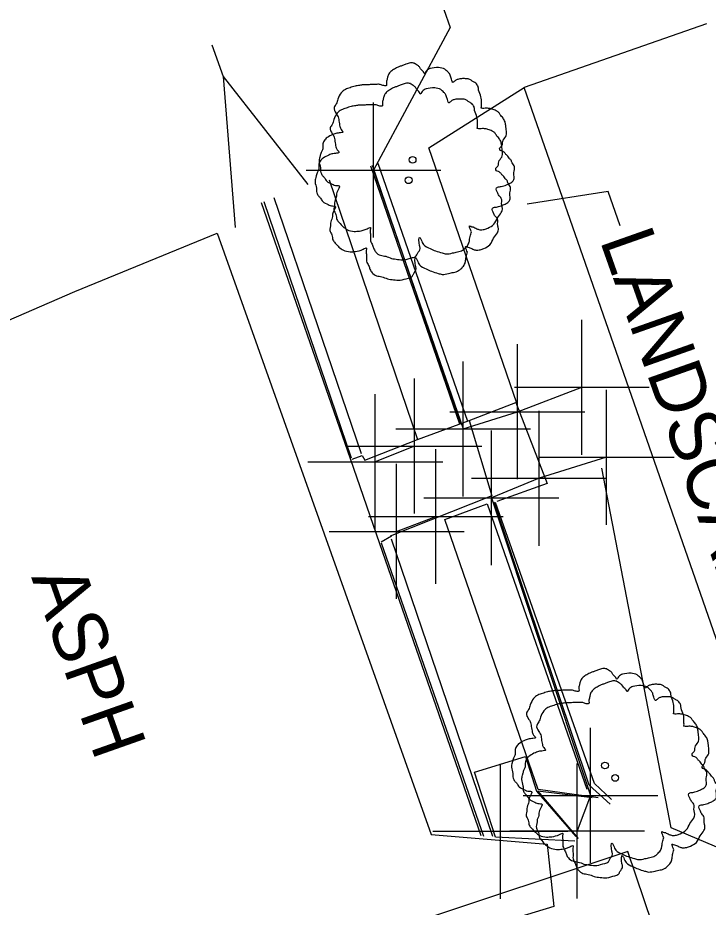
# Model space of a CAD drawing. Extents: x 2004847 to 2009016, y 1134161 to 1140101.
# Drawn here: x 2005808.7 to 2005859.9, y 1138108.9 to 1138174.9 of the extents above; entities that cross this region are included whole.
import ezdxf

# ---------------------------------------------------------------- set-up
doc = ezdxf.new("R2010")
doc.units = 0
for name, color, linetype in [('RD_EX_Bldg', 7, 'Continuous'), ('RD_EX_BldgApp', 7, 'Continuous'), ('RD_EX_Conc', 7, 'Continuous'), ('RD_EX_Driveway', 7, 'Continuous'), ('RD_EX_DV_Prop_txCode', 7, 'Continuous'), ('RD_EX_Misc', 7, 'Continuous'), ('RD_EX_VEG', 7, 'Continuous'), ('RD_Sketch3', 7, 'Continuous')]:
    doc.layers.add(name, color=color, linetype=linetype)

msp = doc.modelspace()

# ---------------------------------------------------------------- linework, layer by layer
at = {"layer": 'RD_EX_Bldg'}
for p in [(2005859.818, 1138174.404), (2005866.841, 1138110.735)]:
    msp.add_line(p, (2005846.292, 1138169.689), dxfattribs=at)
at = {"layer": 'RD_EX_BldgApp'}
msp.add_lwpolyline([(2005842.212, 1138145.001), (2005845.669, 1138146.333), (2005847.999, 1138140.323), (2005844.263, 1138138.993)], dxfattribs=at)
msp.add_lwpolyline([(2005806.418, 1138097.227), (2005810.884, 1138082.901), (2005858.804, 1138098.787), (2005853.984, 1138113.042)], close=True, dxfattribs=at)
at = {"layer": 'RD_EX_Conc'}
for p, q in [((2005835.439, 1138164.08), (2005842.087, 1138144.96)), ((2005834.903, 1138163.888), (2005841.503, 1138144.757)), ((2005835.018, 1138163.927), (2005841.583, 1138144.785)), ((2005831.837, 1138162.853), (2005838.398, 1138143.584)), ((2005834.23, 1138142.524), (2005827.758, 1138161.505)), ((2005833.49, 1138142.212), (2005827.024, 1138161.21)), ((2005843.544, 1138138.815), (2005850.941, 1138117.672)), ((2005843.294, 1138114.166), (2005835.728, 1138135.915)), ((2005843.981, 1138114.174), (2005836.454, 1138136.206))]:
    msp.add_line(p, q, dxfattribs=at)
for points in [[(2005843.113, 1138114.22), (2005835.604, 1138135.853), (2005833.422, 1138142.151), (2005826.827, 1138161.152)], [(2005833.546, 1138142.128), (2005834.283, 1138142.42), (2005834.472, 1138142.054), (2005838.398, 1138143.584), (2005842.212, 1138145.001), (2005843.89, 1138139.424), (2005836.348, 1138136.438), (2005836.459, 1138136.433), (2005835.691, 1138135.983)], [(2005852.678, 1138116.568), (2005851.112, 1138117.98), (2005844.067, 1138138.956)], [(2005851.776, 1138117.023), (2005847.324, 1138117.658), (2005840.411, 1138137.675), (2005843.544, 1138138.815)], [(2005852.787, 1138116.9), (2005851.523, 1138118.105), (2005844.175, 1138138.927)], [(2005850.058, 1138113.813), (2005844.166, 1138114.111), (2005842.613, 1138118.927), (2005846.387, 1138120.092), (2005847.201, 1138117.524), (2005850.127, 1138114.175)], [(2005850.316, 1138114.013), (2005847.31, 1138117.558), (2005851.337, 1138117.052)]]:
    msp.add_lwpolyline(points, dxfattribs=at)
at = {"layer": 'RD_EX_Driveway'}
msp.add_lwpolyline([(2005791.893, 1138145.432), (2005812.971, 1138154.559), (2005823.54, 1138158.89), (2005830.037, 1138140.621), (2005839.408, 1138114.322), (2005848.012, 1138113.597), (2005848.51, 1138108.974), (2005830.681, 1138103.556), (2005807.756, 1138095.979)], dxfattribs=at)
at = {"layer": 'RD_EX_DV_Prop_txCode'}
for p, q in [((2005835.122, 1138158.571), (2005835.122, 1138168.571)), ((2005830.122, 1138163.571), (2005840.122, 1138163.571)), ((2005850.578, 1138142.469), (2005850.578, 1138152.469)), ((2005845.795, 1138140.658), (2005845.795, 1138150.658)), ((2005841.768, 1138139.379), (2005841.768, 1138149.379)), ((2005838.153, 1138138.107), (2005838.153, 1138148.107)), ((2005835.255, 1138136.945), (2005835.255, 1138146.945)), ((2005845.578, 1138147.469), (2005855.578, 1138147.469)), ((2005852.416, 1138137.276), (2005852.416, 1138147.276)), ((2005840.795, 1138145.658), (2005850.795, 1138145.658)), ((2005847.403, 1138135.72), (2005847.403, 1138145.72)), ((2005836.768, 1138144.379), (2005846.768, 1138144.379)), ((2005843.867, 1138134.27), (2005843.867, 1138144.27)), ((2005833.153, 1138143.107), (2005843.153, 1138143.107)), ((2005839.749, 1138132.889), (2005839.749, 1138142.889)), ((2005847.416, 1138142.276), (2005857.416, 1138142.276)), ((2005830.255, 1138141.945), (2005840.255, 1138141.945)), ((2005836.837, 1138131.785), (2005836.837, 1138141.785)), ((2005842.403, 1138140.72), (2005852.403, 1138140.72)), ((2005838.867, 1138139.27), (2005848.867, 1138139.27)), ((2005834.749, 1138137.889), (2005844.749, 1138137.889)), ((2005831.837, 1138136.785), (2005841.837, 1138136.785)), ((2005851.223, 1138112.211), (2005851.223, 1138122.211)), ((2005844.531, 1138109.554), (2005844.531, 1138119.554)), ((2005850.224, 1138109.579), (2005850.224, 1138119.579)), ((2005846.223, 1138117.211), (2005856.223, 1138117.211)), ((2005839.531, 1138114.554), (2005849.531, 1138114.554)), ((2005845.224, 1138114.579), (2005855.224, 1138114.579))]:
    msp.add_line(p, q, dxfattribs=at)
at = {"layer": 'RD_EX_Misc'}
for p, q in [((2005838.153, 1138143.107), (2005835.255, 1138141.945)), ((2005836.837, 1138136.785), (2005839.749, 1138137.889))]:
    msp.add_line(p, q, dxfattribs=at)
for points in [[(2005835.122, 1138163.571), (2005841.768, 1138144.379), (2005845.795, 1138145.658), (2005850.578, 1138147.469)], [(2005852.416, 1138142.276), (2005847.403, 1138140.72), (2005843.867, 1138139.27), (2005851.223, 1138117.211), (2005850.224, 1138114.579)]]:
    msp.add_lwpolyline(points, dxfattribs=at)
at = {"layer": 'RD_EX_VEG'}
for points in [[(2005845.754, 1138146.288), (2005839.234, 1138165.213), (2005846.292, 1138169.689)], [(2005866.841, 1138110.735), (2005857.201, 1138114.796), (2005852.068, 1138141.468)]]:
    msp.add_lwpolyline(points, dxfattribs=at)
for centre, radius in [((2005838.025, 1138164.327), 0.25), ((2005838.012, 1138164.308), 0.0001), ((2005837.729, 1138162.815), 0.25), ((2005837.717, 1138162.796), 0.0001), ((2005852.293, 1138119.427), 0.25), ((2005852.28, 1138119.408), 0.0001), ((2005853.046, 1138118.51), 0.25), ((2005853.033, 1138118.491), 0.0001)]:
    msp.add_circle(centre, radius, dxfattribs=at)
for points in [[(2005838.157, 1138171.494), (2005837.857, 1138171.519), (2005837.532, 1138171.419), (2005837.282, 1138171.319), (2005837.057, 1138171.244), (2005836.833, 1138171.144), (2005836.533, 1138170.97), (2005836.308, 1138170.77), (2005836.183, 1138170.52), (2005836.133, 1138170.295), (2005836.083, 1138170.02), (2005836.083, 1138169.845), (2005835.958, 1138169.82), (2005835.808, 1138169.845), (2005835.558, 1138169.92), (2005835.308, 1138169.92), (2005835.058, 1138169.92), (2005834.708, 1138169.895), (2005834.359, 1138169.895), (2005834.084, 1138169.845), (2005833.759, 1138169.795), (2005833.384, 1138169.67), (2005833.034, 1138169.545), (2005832.734, 1138169.295), (2005832.484, 1138168.82), (2005832.359, 1138168.471), (2005832.21, 1138168.221), (2005832.359, 1138167.771), (2005832.534, 1138167.421), (2005832.559, 1138167.221), (2005832.634, 1138166.796), (2005832.734, 1138166.571), (2005832.859, 1138166.371), (2005832.784, 1138166.347), (2005832.409, 1138166.297), (2005832.11, 1138166.197), (2005831.685, 1138165.972), (2005831.46, 1138165.747), (2005831.36, 1138165.422), (2005831.335, 1138165.072), (2005831.235, 1138164.872), (2005831.16, 1138164.597), (2005831.135, 1138164.522), (2005831.085, 1138164.197), (2005831.185, 1138163.748), (2005831.21, 1138163.398), (2005831.335, 1138163.173), (2005831.485, 1138162.998), (2005831.66, 1138162.748), (2005832.06, 1138162.523), (2005832.384, 1138162.423), (2005832.584, 1138162.398), (2005832.409, 1138161.898), (2005832.359, 1138161.549), (2005832.235, 1138161.149), (2005832.235, 1138161.074), (2005832.185, 1138160.599), (2005832.334, 1138160.274), (2005832.409, 1138159.899), (2005832.584, 1138159.674), (2005832.859, 1138159.375), (2005833.184, 1138159.15), (2005833.684, 1138159.025), (2005834.084, 1138159.05), (2005834.659, 1138159.225), (2005834.908, 1138159.3), (2005834.883, 1138159.125), (2005834.908, 1138158.75), (2005834.908, 1138158.325), (2005835.058, 1138158), (2005835.158, 1138157.725), (2005835.308, 1138157.475), (2005835.633, 1138157.251), (2005836.033, 1138157.176), (2005836.458, 1138157.026), (2005836.908, 1138156.951), (2005837.407, 1138156.926), (2005838.007, 1138157.076), (2005838.282, 1138157.201), (2005838.382, 1138157.375), (2005838.582, 1138157.75), (2005838.532, 1138157.975), (2005838.557, 1138158.575), (2005838.657, 1138158.4), (2005838.832, 1138158.05), (2005839.331, 1138157.75), (2005839.731, 1138157.575), (2005840.206, 1138157.425), (2005840.506, 1138157.35), (2005840.981, 1138157.425), (2005841.356, 1138157.5), (2005841.73, 1138157.625), (2005842.03, 1138157.9), (2005842.205, 1138158.175), (2005842.255, 1138158.45), (2005842.33, 1138158.825), (2005842.38, 1138159)], [(2005842.38, 1138159), (2005842.305, 1138159.175), (2005842.255, 1138159.425), (2005842.33, 1138159.4), (2005842.505, 1138159.35), (2005842.78, 1138159.225), (2005843.005, 1138159.15), (2005843.33, 1138159.175), (2005843.605, 1138159.275), (2005844.054, 1138159.55), (2005844.329, 1138160.024), (2005844.604, 1138160.424), (2005844.679, 1138160.749), (2005844.629, 1138160.974), (2005844.604, 1138161.474), (2005844.404, 1138161.724), (2005844.354, 1138161.848), (2005844.254, 1138162.248), (2005844.329, 1138162.298), (2005844.604, 1138162.348), (2005844.979, 1138162.473), (2005845.254, 1138162.598), (2005845.479, 1138162.773), (2005845.554, 1138162.998), (2005845.529, 1138163.398), (2005845.579, 1138163.798), (2005845.504, 1138163.948), (2005845.404, 1138164.097), (2005845.329, 1138164.297), (2005845.179, 1138164.447), (2005845.079, 1138164.597), (2005844.979, 1138164.697), (2005844.854, 1138164.847), (2005844.679, 1138164.972), (2005844.529, 1138165.022), (2005844.479, 1138165.172), (2005844.629, 1138165.372), (2005844.679, 1138165.472), (2005844.704, 1138165.697), (2005844.929, 1138166.047), (2005844.979, 1138166.446), (2005844.929, 1138166.871), (2005844.879, 1138167.146), (2005844.729, 1138167.421), (2005844.529, 1138167.671), (2005844.404, 1138167.846), (2005844.229, 1138167.971), (2005843.904, 1138168.096), (2005843.655, 1138168.146), (2005843.305, 1138168.146), (2005843.105, 1138168.196), (2005843.13, 1138168.246), (2005843.13, 1138168.396), (2005843.13, 1138168.671), (2005843.055, 1138169.12), (2005842.905, 1138169.62), (2005842.905, 1138169.645), (2005842.805, 1138169.895), (2005842.58, 1138170.095), (2005842.405, 1138170.195), (2005842.205, 1138170.32), (2005841.955, 1138170.345), (2005841.655, 1138170.345), (2005841.381, 1138170.295), (2005841.181, 1138170.195), (2005841.006, 1138170.07), (2005840.931, 1138170.22), (2005840.831, 1138170.52), (2005840.781, 1138170.67), (2005840.631, 1138170.845), (2005840.406, 1138171.044), (2005839.956, 1138171.169), (2005839.331, 1138171.094), (2005839.032, 1138170.895), (2005838.882, 1138170.72), (2005838.832, 1138170.845), (2005838.632, 1138171.044), (2005838.532, 1138171.219), (2005838.357, 1138171.344), (2005838.207, 1138171.444), (2005838.107, 1138171.494)], [(2005837.861, 1138169.982), (2005837.561, 1138170.007), (2005837.237, 1138169.907), (2005836.987, 1138169.807), (2005836.762, 1138169.732), (2005836.537, 1138169.632), (2005836.237, 1138169.457), (2005836.012, 1138169.257), (2005835.887, 1138169.008), (2005835.837, 1138168.783), (2005835.787, 1138168.508), (2005835.787, 1138168.333), (2005835.662, 1138168.308), (2005835.512, 1138168.333), (2005835.262, 1138168.408), (2005835.013, 1138168.408), (2005834.763, 1138168.408), (2005834.413, 1138168.383), (2005834.063, 1138168.383), (2005833.788, 1138168.333), (2005833.463, 1138168.283), (2005833.088, 1138168.158), (2005832.739, 1138168.033), (2005832.439, 1138167.783), (2005832.189, 1138167.308), (2005832.064, 1138166.958), (2005831.914, 1138166.709), (2005832.064, 1138166.259), (2005832.239, 1138165.909), (2005832.264, 1138165.709), (2005832.339, 1138165.284), (2005832.439, 1138165.059), (2005832.564, 1138164.859), (2005832.489, 1138164.834), (2005832.114, 1138164.784), (2005831.814, 1138164.684), (2005831.389, 1138164.46), (2005831.164, 1138164.235), (2005831.064, 1138163.91), (2005831.039, 1138163.56), (2005830.939, 1138163.36), (2005830.864, 1138163.085), (2005830.839, 1138163.01), (2005830.789, 1138162.685), (2005830.889, 1138162.235), (2005830.914, 1138161.886), (2005831.039, 1138161.661), (2005831.189, 1138161.486), (2005831.364, 1138161.236), (2005831.764, 1138161.011), (2005832.089, 1138160.911), (2005832.289, 1138160.886), (2005832.114, 1138160.386), (2005832.064, 1138160.036), (2005831.939, 1138159.637), (2005831.939, 1138159.562), (2005831.889, 1138159.087), (2005832.039, 1138158.762), (2005832.114, 1138158.387), (2005832.289, 1138158.162), (2005832.564, 1138157.862), (2005832.888, 1138157.638), (2005833.388, 1138157.513), (2005833.788, 1138157.538), (2005834.363, 1138157.712), (2005834.613, 1138157.787), (2005834.588, 1138157.613), (2005834.613, 1138157.238), (2005834.613, 1138156.813), (2005834.763, 1138156.488), (2005834.863, 1138156.213), (2005835.013, 1138155.963), (2005835.337, 1138155.738), (2005835.737, 1138155.663), (2005836.162, 1138155.513), (2005836.612, 1138155.438), (2005837.112, 1138155.413), (2005837.711, 1138155.563), (2005837.986, 1138155.688), (2005838.086, 1138155.863), (2005838.286, 1138156.238), (2005838.236, 1138156.463), (2005838.261, 1138157.063), (2005838.361, 1138156.888), (2005838.536, 1138156.538), (2005839.036, 1138156.238), (2005839.436, 1138156.063), (2005839.91, 1138155.913), (2005840.21, 1138155.838), (2005840.685, 1138155.913), (2005841.06, 1138155.988), (2005841.435, 1138156.113), (2005841.735, 1138156.388), (2005841.91, 1138156.663), (2005841.96, 1138156.938), (2005842.034, 1138157.313), (2005842.084, 1138157.488)], [(2005842.084, 1138157.488), (2005842.01, 1138157.663), (2005841.96, 1138157.912), (2005842.034, 1138157.887), (2005842.209, 1138157.837), (2005842.484, 1138157.712), (2005842.709, 1138157.638), (2005843.034, 1138157.663), (2005843.309, 1138157.762), (2005843.759, 1138158.037), (2005844.034, 1138158.512), (2005844.308, 1138158.912), (2005844.383, 1138159.237), (2005844.333, 1138159.462), (2005844.308, 1138159.961), (2005844.109, 1138160.211), (2005844.059, 1138160.336), (2005843.959, 1138160.736), (2005844.034, 1138160.786), (2005844.308, 1138160.836), (2005844.683, 1138160.961), (2005844.958, 1138161.086), (2005845.183, 1138161.261), (2005845.258, 1138161.486), (2005845.233, 1138161.886), (2005845.283, 1138162.285), (2005845.208, 1138162.435), (2005845.108, 1138162.585), (2005845.033, 1138162.785), (2005844.883, 1138162.935), (2005844.783, 1138163.085), (2005844.683, 1138163.185), (2005844.558, 1138163.335), (2005844.383, 1138163.46), (2005844.234, 1138163.51), (2005844.184, 1138163.66), (2005844.333, 1138163.86), (2005844.383, 1138163.96), (2005844.408, 1138164.185), (2005844.633, 1138164.534), (2005844.683, 1138164.934), (2005844.633, 1138165.359), (2005844.583, 1138165.634), (2005844.433, 1138165.909), (2005844.234, 1138166.159), (2005844.109, 1138166.334), (2005843.934, 1138166.459), (2005843.609, 1138166.584), (2005843.359, 1138166.634), (2005843.009, 1138166.634), (2005842.809, 1138166.684), (2005842.834, 1138166.734), (2005842.834, 1138166.883), (2005842.834, 1138167.158), (2005842.759, 1138167.608), (2005842.609, 1138168.108), (2005842.609, 1138168.133), (2005842.509, 1138168.383), (2005842.284, 1138168.583), (2005842.109, 1138168.683), (2005841.91, 1138168.808), (2005841.66, 1138168.833), (2005841.36, 1138168.833), (2005841.085, 1138168.783), (2005840.885, 1138168.683), (2005840.71, 1138168.558), (2005840.635, 1138168.708), (2005840.535, 1138169.008), (2005840.485, 1138169.157), (2005840.335, 1138169.332), (2005840.11, 1138169.532), (2005839.66, 1138169.657), (2005839.036, 1138169.582), (2005838.736, 1138169.382), (2005838.586, 1138169.207), (2005838.536, 1138169.332), (2005838.336, 1138169.532), (2005838.236, 1138169.707), (2005838.061, 1138169.832), (2005837.911, 1138169.932), (2005837.811, 1138169.982)], [(2005852.425, 1138126.594), (2005852.125, 1138126.619), (2005851.8, 1138126.519), (2005851.55, 1138126.419), (2005851.325, 1138126.344), (2005851.101, 1138126.244), (2005850.801, 1138126.069), (2005850.576, 1138125.87), (2005850.451, 1138125.62), (2005850.401, 1138125.395), (2005850.351, 1138125.12), (2005850.351, 1138124.945), (2005850.226, 1138124.92), (2005850.076, 1138124.945), (2005849.826, 1138125.02), (2005849.576, 1138125.02), (2005849.326, 1138125.02), (2005848.976, 1138124.995), (2005848.627, 1138124.995), (2005848.352, 1138124.945), (2005848.027, 1138124.895), (2005847.652, 1138124.77), (2005847.302, 1138124.645), (2005847.002, 1138124.395), (2005846.752, 1138123.92), (2005846.627, 1138123.571), (2005846.478, 1138123.321), (2005846.627, 1138122.871), (2005846.802, 1138122.521), (2005846.827, 1138122.321), (2005846.902, 1138121.896), (2005847.002, 1138121.671), (2005847.127, 1138121.471), (2005847.052, 1138121.447), (2005846.677, 1138121.397), (2005846.378, 1138121.297), (2005845.953, 1138121.072), (2005845.728, 1138120.847), (2005845.628, 1138120.522), (2005845.603, 1138120.172), (2005845.503, 1138119.972), (2005845.428, 1138119.697), (2005845.403, 1138119.622), (2005845.353, 1138119.297), (2005845.453, 1138118.848), (2005845.478, 1138118.498), (2005845.603, 1138118.273), (2005845.753, 1138118.098), (2005845.928, 1138117.848), (2005846.328, 1138117.623), (2005846.652, 1138117.523), (2005846.852, 1138117.498), (2005846.677, 1138116.998), (2005846.627, 1138116.649), (2005846.503, 1138116.249), (2005846.503, 1138116.174), (2005846.453, 1138115.699), (2005846.602, 1138115.374), (2005846.677, 1138114.999), (2005846.852, 1138114.774), (2005847.127, 1138114.475), (2005847.452, 1138114.25), (2005847.952, 1138114.125), (2005848.352, 1138114.15), (2005848.927, 1138114.325), (2005849.176, 1138114.4), (2005849.151, 1138114.225), (2005849.176, 1138113.85), (2005849.176, 1138113.425), (2005849.326, 1138113.1), (2005849.426, 1138112.825), (2005849.576, 1138112.575), (2005849.901, 1138112.35), (2005850.301, 1138112.275), (2005850.726, 1138112.126), (2005851.176, 1138112.051), (2005851.675, 1138112.026), (2005852.275, 1138112.175), (2005852.55, 1138112.3), (2005852.65, 1138112.475), (2005852.85, 1138112.85), (2005852.8, 1138113.075), (2005852.825, 1138113.675), (2005852.925, 1138113.5), (2005853.1, 1138113.15), (2005853.599, 1138112.85), (2005853.999, 1138112.675), (2005854.474, 1138112.525), (2005854.774, 1138112.45), (2005855.249, 1138112.525), (2005855.624, 1138112.6), (2005855.998, 1138112.725), (2005856.298, 1138113), (2005856.473, 1138113.275), (2005856.523, 1138113.55), (2005856.598, 1138113.925), (2005856.648, 1138114.1)], [(2005856.648, 1138114.1), (2005856.573, 1138114.275), (2005856.523, 1138114.525), (2005856.598, 1138114.499), (2005856.773, 1138114.45), (2005857.048, 1138114.325), (2005857.273, 1138114.25), (2005857.598, 1138114.275), (2005857.873, 1138114.375), (2005858.322, 1138114.65), (2005858.597, 1138115.124), (2005858.872, 1138115.524), (2005858.947, 1138115.849), (2005858.897, 1138116.074), (2005858.872, 1138116.574), (2005858.672, 1138116.823), (2005858.622, 1138116.948), (2005858.522, 1138117.348), (2005858.597, 1138117.398), (2005858.872, 1138117.448), (2005859.247, 1138117.573), (2005859.522, 1138117.698), (2005859.747, 1138117.873), (2005859.822, 1138118.098), (2005859.797, 1138118.498), (2005859.847, 1138118.898), (2005859.772, 1138119.048), (2005859.672, 1138119.197), (2005859.597, 1138119.397), (2005859.447, 1138119.547), (2005859.347, 1138119.697), (2005859.247, 1138119.797), (2005859.122, 1138119.947), (2005858.947, 1138120.072), (2005858.797, 1138120.122), (2005858.747, 1138120.272), (2005858.897, 1138120.472), (2005858.947, 1138120.572), (2005858.972, 1138120.797), (2005859.197, 1138121.147), (2005859.247, 1138121.546), (2005859.197, 1138121.971), (2005859.147, 1138122.246), (2005858.997, 1138122.521), (2005858.797, 1138122.771), (2005858.672, 1138122.946), (2005858.497, 1138123.071), (2005858.172, 1138123.196), (2005857.923, 1138123.246), (2005857.573, 1138123.246), (2005857.373, 1138123.296), (2005857.398, 1138123.346), (2005857.398, 1138123.496), (2005857.398, 1138123.771), (2005857.323, 1138124.22), (2005857.173, 1138124.72), (2005857.173, 1138124.745), (2005857.073, 1138124.995), (2005856.848, 1138125.195), (2005856.673, 1138125.295), (2005856.473, 1138125.42), (2005856.223, 1138125.445), (2005855.923, 1138125.445), (2005855.649, 1138125.395), (2005855.449, 1138125.295), (2005855.274, 1138125.17), (2005855.199, 1138125.32), (2005855.099, 1138125.62), (2005855.049, 1138125.77), (2005854.899, 1138125.944), (2005854.674, 1138126.144), (2005854.224, 1138126.269), (2005853.599, 1138126.194), (2005853.3, 1138125.995), (2005853.15, 1138125.82), (2005853.1, 1138125.944), (2005852.9, 1138126.144), (2005852.8, 1138126.319), (2005852.625, 1138126.444), (2005852.475, 1138126.544), (2005852.375, 1138126.594)], [(2005853.178, 1138125.677), (2005852.878, 1138125.702), (2005852.553, 1138125.602), (2005852.303, 1138125.502), (2005852.078, 1138125.427), (2005851.853, 1138125.327), (2005851.554, 1138125.153), (2005851.329, 1138124.953), (2005851.204, 1138124.703), (2005851.154, 1138124.478), (2005851.104, 1138124.203), (2005851.104, 1138124.028), (2005850.979, 1138124.003), (2005850.829, 1138124.028), (2005850.579, 1138124.103), (2005850.329, 1138124.103), (2005850.079, 1138124.103), (2005849.729, 1138124.078), (2005849.379, 1138124.078), (2005849.105, 1138124.028), (2005848.78, 1138123.978), (2005848.405, 1138123.853), (2005848.055, 1138123.728), (2005847.755, 1138123.478), (2005847.505, 1138123.004), (2005847.38, 1138122.654), (2005847.23, 1138122.404), (2005847.38, 1138121.954), (2005847.555, 1138121.604), (2005847.58, 1138121.404), (2005847.655, 1138120.979), (2005847.755, 1138120.755), (2005847.88, 1138120.555), (2005847.805, 1138120.53), (2005847.43, 1138120.48), (2005847.13, 1138120.38), (2005846.706, 1138120.155), (2005846.481, 1138119.93), (2005846.381, 1138119.605), (2005846.356, 1138119.255), (2005846.256, 1138119.055), (2005846.181, 1138118.78), (2005846.156, 1138118.705), (2005846.106, 1138118.381), (2005846.206, 1138117.931), (2005846.231, 1138117.581), (2005846.356, 1138117.356), (2005846.506, 1138117.181), (2005846.681, 1138116.931), (2005847.08, 1138116.706), (2005847.405, 1138116.606), (2005847.605, 1138116.581), (2005847.43, 1138116.082), (2005847.38, 1138115.732), (2005847.255, 1138115.332), (2005847.255, 1138115.257), (2005847.205, 1138114.782), (2005847.355, 1138114.457), (2005847.43, 1138114.082), (2005847.605, 1138113.858), (2005847.88, 1138113.558), (2005848.205, 1138113.333), (2005848.705, 1138113.208), (2005849.105, 1138113.233), (2005849.679, 1138113.408), (2005849.929, 1138113.483), (2005849.904, 1138113.308), (2005849.929, 1138112.933), (2005849.929, 1138112.508), (2005850.079, 1138112.183), (2005850.179, 1138111.908), (2005850.329, 1138111.658), (2005850.654, 1138111.434), (2005851.054, 1138111.359), (2005851.479, 1138111.209), (2005851.928, 1138111.134), (2005852.428, 1138111.109), (2005853.028, 1138111.259), (2005853.303, 1138111.384), (2005853.403, 1138111.559), (2005853.603, 1138111.933), (2005853.553, 1138112.158), (2005853.578, 1138112.758), (2005853.678, 1138112.583), (2005853.853, 1138112.233), (2005854.352, 1138111.933), (2005854.752, 1138111.758), (2005855.227, 1138111.608), (2005855.527, 1138111.534), (2005856.002, 1138111.608), (2005856.376, 1138111.683), (2005856.751, 1138111.808), (2005857.051, 1138112.083), (2005857.226, 1138112.358), (2005857.276, 1138112.633), (2005857.351, 1138113.008), (2005857.401, 1138113.183)], [(2005857.401, 1138113.183), (2005857.326, 1138113.358), (2005857.276, 1138113.608), (2005857.351, 1138113.583), (2005857.526, 1138113.533), (2005857.801, 1138113.408), (2005858.026, 1138113.333), (2005858.351, 1138113.358), (2005858.625, 1138113.458), (2005859.075, 1138113.733), (2005859.35, 1138114.207), (2005859.625, 1138114.607), (2005859.7, 1138114.932), (2005859.65, 1138115.157), (2005859.625, 1138115.657), (2005859.425, 1138115.907), (2005859.375, 1138116.032), (2005859.275, 1138116.431), (2005859.35, 1138116.481), (2005859.625, 1138116.531), (2005860, 1138116.656), (2005860.275, 1138116.781), (2005860.5, 1138116.956), (2005860.575, 1138117.181), (2005860.55, 1138117.581), (2005860.6, 1138117.981), (2005860.525, 1138118.131), (2005860.425, 1138118.281), (2005860.35, 1138118.481), (2005860.2, 1138118.63), (2005860.1, 1138118.78), (2005860, 1138118.88), (2005859.875, 1138119.03), (2005859.7, 1138119.155), (2005859.55, 1138119.205), (2005859.5, 1138119.355), (2005859.65, 1138119.555), (2005859.7, 1138119.655), (2005859.725, 1138119.88), (2005859.95, 1138120.23), (2005860, 1138120.63), (2005859.95, 1138121.054), (2005859.9, 1138121.329), (2005859.75, 1138121.604), (2005859.55, 1138121.854), (2005859.425, 1138122.029), (2005859.25, 1138122.154), (2005858.925, 1138122.279), (2005858.675, 1138122.329), (2005858.326, 1138122.329), (2005858.126, 1138122.379), (2005858.151, 1138122.429), (2005858.151, 1138122.579), (2005858.151, 1138122.854), (2005858.076, 1138123.303), (2005857.926, 1138123.803), (2005857.926, 1138123.828), (2005857.826, 1138124.078), (2005857.601, 1138124.278), (2005857.426, 1138124.378), (2005857.226, 1138124.503), (2005856.976, 1138124.528), (2005856.676, 1138124.528), (2005856.401, 1138124.478), (2005856.201, 1138124.378), (2005856.027, 1138124.253), (2005855.952, 1138124.403), (2005855.852, 1138124.703), (2005855.802, 1138124.853), (2005855.652, 1138125.028), (2005855.427, 1138125.228), (2005854.977, 1138125.352), (2005854.352, 1138125.278), (2005854.052, 1138125.078), (2005853.902, 1138124.903), (2005853.853, 1138125.028), (2005853.653, 1138125.228), (2005853.553, 1138125.402), (2005853.378, 1138125.527), (2005853.228, 1138125.627), (2005853.128, 1138125.677)]]:
    msp.add_spline(points, degree=3, dxfattribs=at)
at = {"layer": 'RD_Sketch3'}
msp.add_line((2005823.973, 1138170.5), (2005824.871, 1138159.313), dxfattribs=at)
for points in [[(2005840.329, 1138175.466), (2005840.799, 1138174.135), (2005835.122, 1138163.571)], [(2005823.144, 1138172.847), (2005823.973, 1138170.5), (2005830.253, 1138162.49)], [(2005853.416, 1138159.437), (2005852.516, 1138161.983), (2005846.531, 1138161.041)]]:
    msp.add_lwpolyline(points, dxfattribs=at)

# ---------------------------------------------------------------- texts
for s, p in [('LANDSCAPE', (2005851.884, 1138158.38)), ('ASPH', (2005809.72, 1138133.398))]:
    msp.add_text(s, height=4, rotation=289.44941, dxfattribs=at).set_placement(p)

doc.saveas('drawing.dxf')
